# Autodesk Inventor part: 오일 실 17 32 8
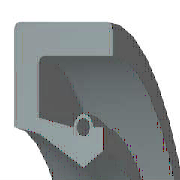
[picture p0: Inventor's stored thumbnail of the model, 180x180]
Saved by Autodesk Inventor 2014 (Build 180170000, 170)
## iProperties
IsCustomPart: 1
Created: 2012-02
Part Number: 오일 실 17 32 8
Material: 고무
Description: 오일-실
Document SubType Name: Modeling
Standard: KS B 2804
Designer: test
Standards Organization: KS
Language: ko-KR
Size Designation: S - 17 32 8
Categories: <MemberInstance><Categories><Category DisplayName="샤프트 부품" InternalName="7f7aeb1f-a693-4053-b835-cee3144e0d98" Mnemonic="SHFT"><Category DisplayName="실링" Intern
Density: 0.93 g/cm^3
Appearance: 고무 - 검은색 - 버전 1.1
Mass: 1.89534 g
Surface Area: 30.829 cm^2
Volume: 2.038 cm^3
Author: test
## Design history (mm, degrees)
revolve "본체" stored, may be unused: angle "d17" = 90 deg
revolve "스프링1" stored, may be unused: angle "d18" = 90 deg
body "Solid1"
sketch "스케치1"
  geometry: L1 (0, 16)-(8, 16); L2 (8, 16)-(8, 14.75); L3 (8, 14.75)-(1.75, 14.75); L4 (0, 16)-(0, 10.6); L5 (0, 10.6)-(1.75, 10.25); L6 (1.75, 10.25)-(4.9, 8.5); L7 (4.9, 8.5)-(0, 8.5); L8 (6.3, 9.375)-(6.3, 10.6); L9 (0, 0)-(9.586, 0) reference; L10 (4.9, 8.5)-(6.3, 9.375); L11 (0, 18)-(0, -3) reference; L12 (-1.917, 0)-(11.503, 0) reference; L13 (4.2, 10.6)-(1.75, 11.09); L14 (1.75, 11.09)-(1.75, 14.75); L15 (6.3, 10.6)-(5.6, 10.6); C1 r 0.455 at (4.9, 10.6); A1 r 0.7 centre (4.9, 10.6) between (5.6, 10.6) and (4.2, 10.6)
  constraints: 26 end point, 5 horizontal alignment, 4 perpendicular, 2 centre point, 2 collinear, 2 horizontal, 2 parallel, 2 point on circle, 2 point on line, 2 vertical alignment, 1 coincident
  dimensions: "d0" = 32 diameter of L1 L9 (= SD2); "d1" = 18.75 diameter of L8.start L9 (= ABDM); "d2" = 1.25 distance of L1.end L2.end (computed from SD); "d3" = 0.91 diameter of C1 (= SPDI); "d4" = 1.4 diameter of A1 (= SPDA); "d5" = 17 diameter of L6.end L9 (= NND); "d6" = 20.5 diameter of L5.end L9 (= TKDM); "d7" = 21.2 diameter of L4.end L9 (= HLDM); "d8" = 4.9 distance from line of C1.centre L4 (= SPDST); "d9" = 6.3 distance between parallel lines of L8 L4 (= SDI); "d10" = 8 distance between parallel lines of L2 L4 (= SWDT); "d12" = 1.75 distance between parallel lines of L14 L4 (= SD)
fillet "모깎기1" dims "d11" = 0.3 (= RR)
other parameters: "SD2" = 32 [user parameter; used in 1 equation term], "SWDT" = 8 [user parameter; used in 1 equation term], "RR" = 0.3 [user parameter; used in 1 equation term], "SD" = 1.75 [user parameter; used in 2 equation terms], "NND" = 17 [user parameter; used in 1 equation term], "SPDA" = 1.4 [user parameter; used in 1 equation term], "SPDI" = 0.91 [user parameter; used in 1 equation term], "TKDM" = 20.5 [user parameter; used in 1 equation term], "HLDM" = 21.2 [user parameter; used in 1 equation term], "ABDM" = 18.75 [user parameter; used in 1 equation term], "SDI" = 6.3 [user parameter; used in 1 equation term], "SPDST" = 4.9 [user parameter; used in 1 equation term], "d13" = 0, "d14" = 0, "d15" = 0, "LAB" = 0.35 [user parameter]
